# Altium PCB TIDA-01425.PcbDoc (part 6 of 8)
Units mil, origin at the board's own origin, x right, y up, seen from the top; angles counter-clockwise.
Board outline 7000 x 3600 mil, 6 copper layers (Layer 1 - Top Layer, Layer 2 - GND, Layer 3 - Signal / PWR, Layer 4 - Signal / PWR, Layer 5 - PWR, Layer 6 - Bottom Layer), stack 60.4 mil thick; 495 components, 307 nets, 2058 pads, 1870 vias.
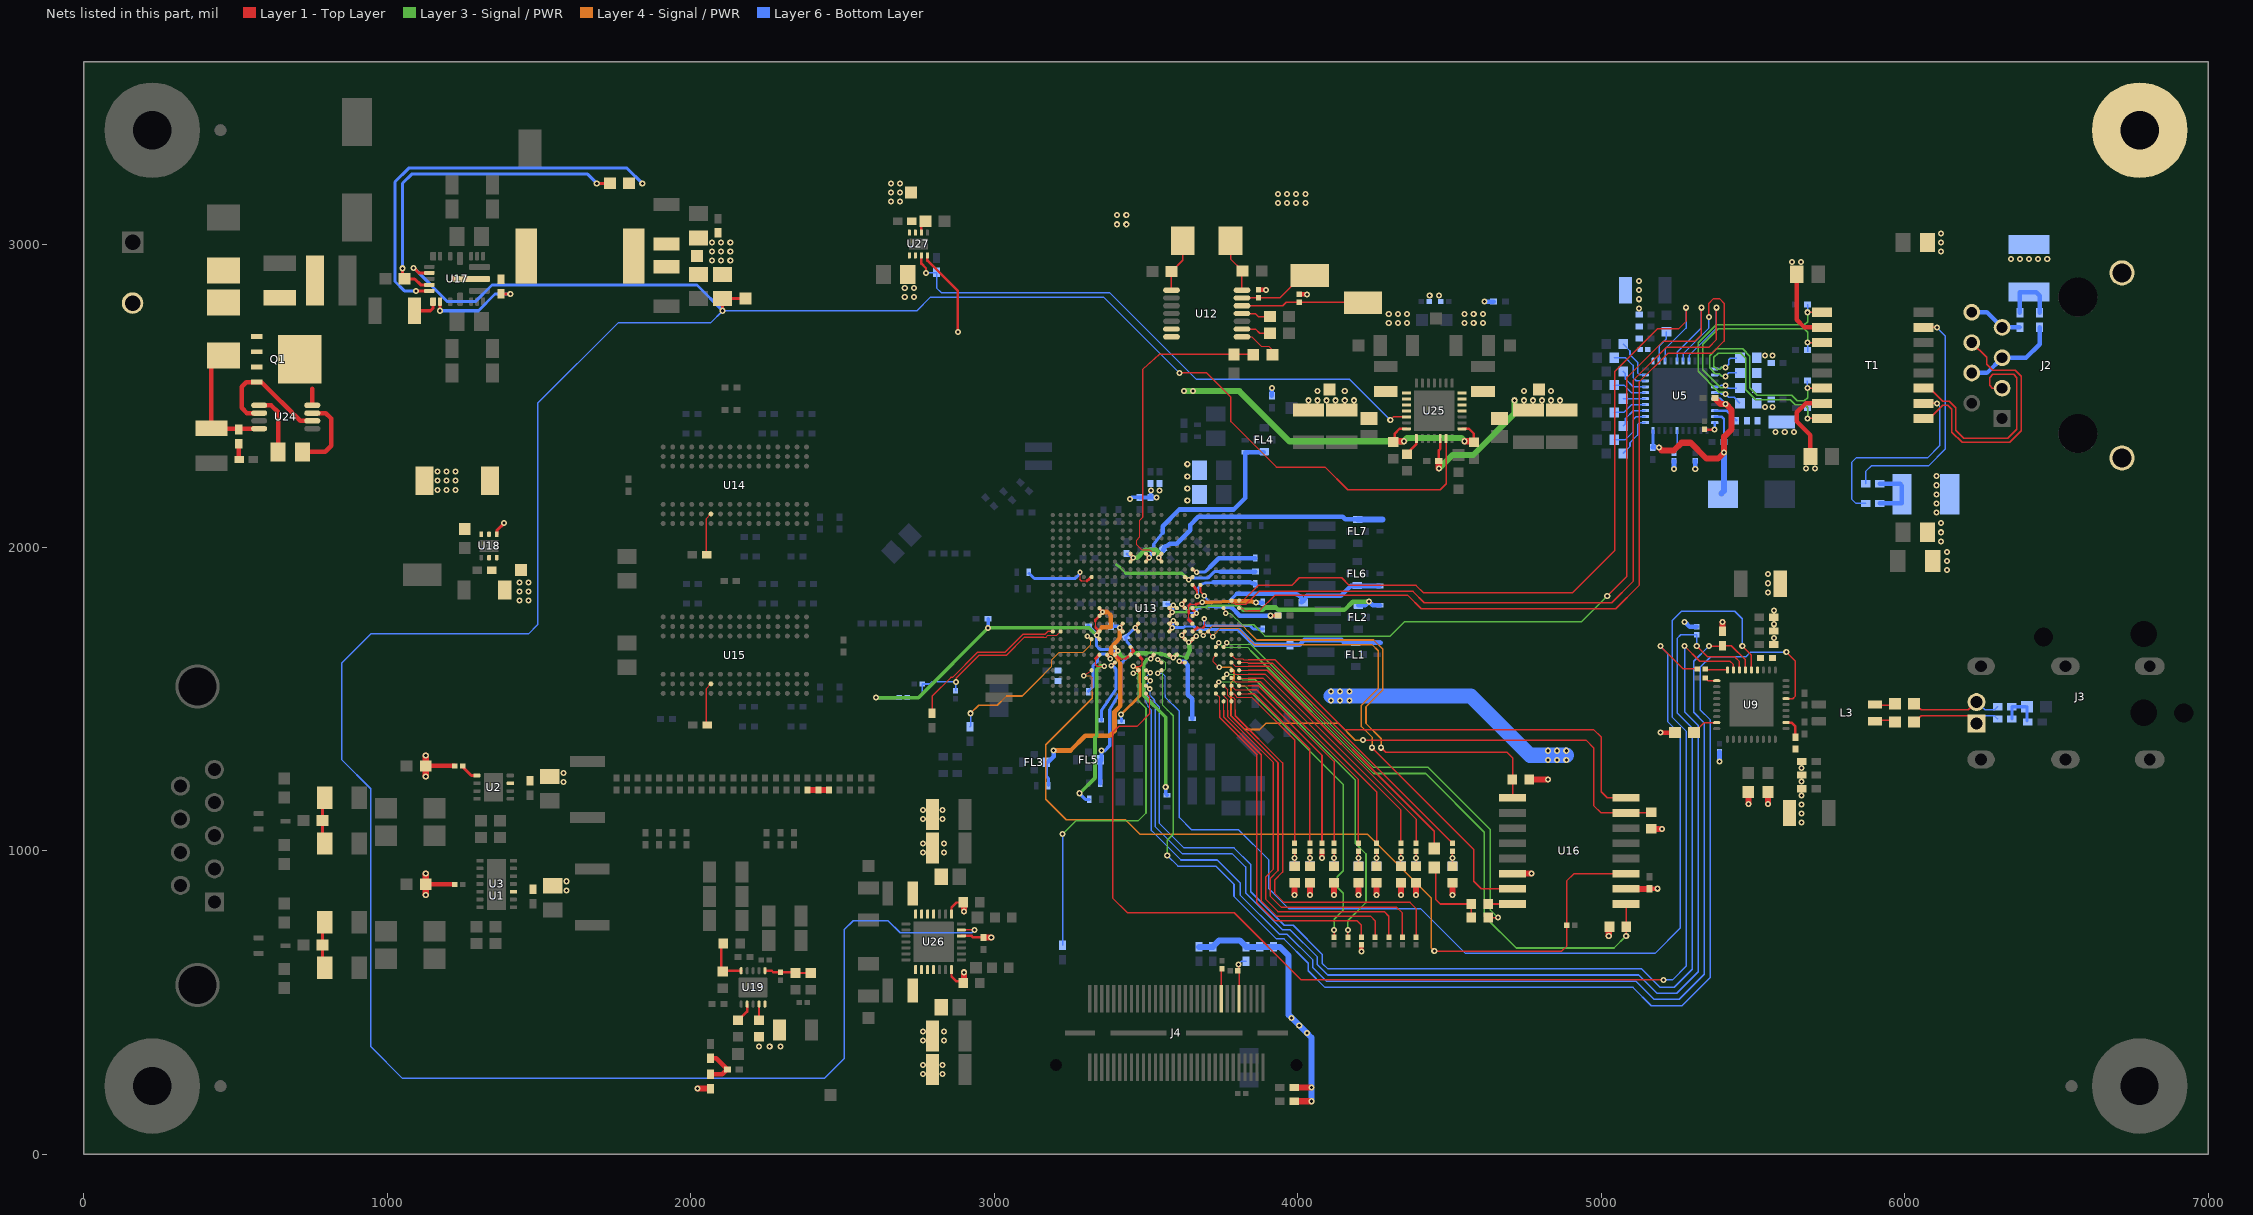
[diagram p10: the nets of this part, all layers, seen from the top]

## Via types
v1: diameter 20, hole 10, Layer 1 - Top Layer to Layer 6 - Bottom Layer, tented both sides, 1119 vias
v2: diameter 20, hole 9.99, Layer 1 - Top Layer to Layer 6 - Bottom Layer, tented both sides, 298 vias
v3: diameter 18, hole 7.99, Layer 1 - Top Layer to Layer 6 - Bottom Layer, tented both sides, 203 vias
v4: diameter 18, hole 8, Layer 1 - Top Layer to Layer 6 - Bottom Layer, tented both sides, 177 vias
v5: diameter 19.68, hole 7.87, Layer 1 - Top Layer to Layer 6 - Bottom Layer, tented both sides, 41 vias
v6: diameter 20, hole 10, Layer 1 - Top Layer to Layer 6 - Bottom Layer, 27 vias
v7: diameter 19.68, hole 7.87, Layer 1 - Top Layer to Layer 6 - Bottom Layer, 5 vias

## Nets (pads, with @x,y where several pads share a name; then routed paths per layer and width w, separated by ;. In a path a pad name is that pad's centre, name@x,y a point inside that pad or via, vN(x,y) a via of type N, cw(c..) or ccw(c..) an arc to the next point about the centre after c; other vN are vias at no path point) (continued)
MII0_TX_D1: U5.5 U13.N3 | length 2709.4
  Layer 1 - Top Layer w4: U13.N3@3755.91,1800 v3(3763.5,1783.6)
  Layer 1 - Top Layer w5: v2(5020,1840) 5085,1905 5085,2560 5205,2680 5310,2680 5330,2700 v6(5330,2790)
  Layer 3 - Signal / PWR w4: v3(3763.5,1783.6) 3778,1783.6 3816.47,1745.13 3837,1745.13
  Layer 3 - Signal / PWR w5.25: 3837,1745.13 3854.87,1745.13 3892,1708 4305,1708 4352,1755 4935,1755 v2(5020,1840)
  Layer 6 - Bottom Layer w5: U5.5@5250.16,2614.17 5250.16,2643.16 5330,2723 v6(5330,2790)
MII0_TX_D2: U5.6 U13.N1 | length 2811.6
  Layer 1 - Top Layer w4: U13.N1@3807.09,1800 3817.02,1800 3825.12,1791.9 3837,1791.9
  Layer 1 - Top Layer w5: 3837,1791.9 3874.09,1791.9 3924.2,1842 4363,1842 4407,1798 5048,1798 5125,1875 5125,2545 5220,2640 5365,2640 5405,2680 5405,2805 5390,2820 5370,2820 5355,2805 v6(5355,2760)
  Layer 6 - Bottom Layer w5: U5.6@5269.84,2614.17 5269.84,2637.84 5355,2723 v6(5355,2760)
MII0_TX_D3: U5.7 U13.P2 | length 2701.7
  Layer 1 - Top Layer w4: U13.P2@3781.5,1825.59 3794.19,1812.9 3829.15,1812.9
  Layer 1 - Top Layer w5: 3829.15,1812.9 3871.26,1855 4380,1855 4417,1818 5035,1818 5105,1888 5105,2550 5215,2660 5355,2660 5380,2685 v6(5380,2790)
  Layer 6 - Bottom Layer w5: U5.7@5289.53,2614.17 5289.53,2632.53 5380,2723 v6(5380,2790)
MII0_TX_EN: U5.3 U13.P1 | length 2490.3
  Layer 1 - Top Layer w4: U13.P1@3807.09,1825.59 3820.59,1825.59 3837,1842
  Layer 1 - Top Layer w5: 3837,1842 3840.99,1845.99 3841.14,1845.99 3870.16,1875 3980,1875 4005,1900 4145,1900 4170,1875 4390,1875 4415,1850 4905,1850 5045,1990 5045,2580 5185,2720 5255,2720 5280,2745 v6(5280,2790)
  Layer 6 - Bottom Layer w5: U5.3@5210.79,2614.17 5210.79,2653.79 5280,2723 v6(5280,2790)
NetC2_1: C2.1 R5.1 R7.2 | length 155.3
  Layer 1 - Top Layer w10: R7.2@792.91,615 786.5,621.42 C2.1@786.5,690 786.5,758.58 R5.1@792.91,765
NetC8_2: C8.2 C11.2 C12.2 C13.1 U5.16 U5.19 U5.30 | length 882.3
  Layer 1 - Top Layer w20: v1(5190,2329.69) 5199.69,2320 5240,2320 5265,2345 5295,2345 5347,2293 5385,2293 v1(5405,2313) 5405,2365 5430,2390 5430,2453 v1(5410,2473) 5393,2473 C8.2@5374.69,2491.31
  Layer 6 - Bottom Layer w8: U5.19@5374.17,2431.1 5396.9,2431.1 5404.69,2423.31 C12.2@5404.69,2348 ; U5.16@5374.17,2490.16 5392.84,2490.16 v1(5410,2473)
  Layer 6 - Bottom Layer w10: C11.2@5171.42,2329.69 U5.30@5171.42,2385.83
  Layer 6 - Bottom Layer w15: C11.2@5170,2329.69 5171.42,2329.69 v1(5190,2329.69)
  Layer 6 - Bottom Layer w20: C13.1@5396.5,2178 5404.69,2186.19 C12.2@5404.69,2348
NetC15_1: C15.1 C31.1 FL1.3 U13.K10 U13.L9 U13.L10 | length 810.9
  Layer 1 - Top Layer w10: U13.K10@3576.77,1723.23 v3(3586.5,1736) U13.L10@3576.77,1748.82 v3(3589.8,1758.7) U13.L9@3602.36,1748.82
  Layer 6 - Bottom Layer w6: 3627.2,1739 3659.2,1739
  Layer 6 - Bottom Layer w10: v3(3586.5,1736) 3624.2,1736 3627.2,1739 ; 3659.2,1739 3669.19,1729.01 3806.2,1729.01 3808.71,1726.5
  Layer 6 - Bottom Layer w12: v3(3586.5,1736) v3(3589.8,1758.7)
  Layer 6 - Bottom Layer w15: 3808.71,1726.5 3855.83,1679.38 C15.1@3975,1679.38 4006.38,1679.38 4022,1695 4144.3,1695 4152.93,1686.37 FL1.3@4191,1686.37 4274,1686.37
NetC20_1: C20.1 J3.2 R27.2 | length 306.3
  Layer 1 - Top Layer w5: C20.1@6031.5,1485 6055,1465 6210,1465 J3.2@6236.93,1490.43
  Layer 6 - Bottom Layer w5: J3.2@6236.93,1490.43 6265,1465 6296.38,1465 R27.2@6306.38,1475
NetC20_2: C20.2 L3.1 | length 70
  Layer 1 - Top Layer w5: L3.1@5900,1480 C20.2@5970,1480
NetC26_1: C26.1 J3.1 R26.2 | length 306.3
  Layer 1 - Top Layer w5: C26.1@6031.5,1425 6055,1445 6210,1445 J3.1@6236.93,1419.57
  Layer 6 - Bottom Layer w5: J3.1@6236.93,1419.57 6265,1445 6296.38,1445 R26.2@6306.38,1435
NetC26_2: C26.2 L3.4 | length 70
  Layer 1 - Top Layer w5: L3.4@5900,1430 C26.2@5970,1430
NetC28_1: C28.1 R26.1 R27.1 R28.2 | length 132
  Layer 6 - Bottom Layer w10: R26.1@6353.62,1435 R27.1@6353.62,1475 C28.1@6398.5,1475 ; R28.2@6403.5,1427.87 C28.1@6403.5,1475
NetC34_1: C34.1 C35.1 FL2.3 U13.M10 U13.N9 U13.N10 | length 871.1
  Layer 1 - Top Layer w10: U13.M10@3576.77,1774.41 v3(3586.7,1787.1) U13.N10@3576.77,1800 v3(3589.6,1809.6) U13.N9@3602.36,1800
  Layer 3 - Signal / PWR w6: 3666.99,1803.01 3699.01,1803.01
  Layer 3 - Signal / PWR w8: v3(3586.7,1787.1) 3632.1,1787.1 3648.01,1803.01 3666.99,1803.01 ; 3699.01,1803.01 3703.58,1807.58 3749.45,1807.58 3750.5,1808.63 3806.37,1808.63 3820,1795
  Layer 3 - Signal / PWR w15: 3820,1795 3884.99,1795 3892.09,1802.1 3927.91,1802.1 3936.01,1794 4154,1794 4181.2,1821.2 v1(4234.9,1821.2)
  Layer 6 - Bottom Layer w10: C34.1@3567.5,1813 v3(3589.6,1809.6)
  Layer 6 - Bottom Layer w12: v3(3586.7,1787.1) v3(3589.6,1809.6)
  Layer 6 - Bottom Layer w15: FL2.3@4200,1809 4222.7,1809 v1(4234.9,1821.2) 4247.1,1809 C35.1@4271.2,1809
NetC36_1: C36.1 C41.1 FL3.3 U13.K16 U13.L16 | length 784.7
  Layer 1 - Top Layer w10: U13.K16@3423.23,1723.23 v3(3413.4,1736) U13.L16@3423.23,1748.82
  Layer 4 - Signal / PWR w10: 3384.7,1653.6 3392.5,1648.1 3401.21,1639.39 3415,1616.64
  Layer 4 - Signal / PWR w15: v1(3195.8,1330.81) 3251.33,1330.81 3299.34,1379.87 3381.07,1379.87 3396.2,1395 3396.2,1458.71 3401.46,1464 3415,1477.62 3415,1616.64 ; 3384.7,1653.6 3385.9,1669.9 3413.1,1702.2 v3(3413.4,1736)
  Layer 6 - Bottom Layer w10: FL3.3@3171.37,1292 3171.37,1245.63 3178,1239 C41.1@3178,1215 ; FL3.3@3176.4,1291.7 FL3.3@3179.7,1295 ; C36.1@3387.1,1740.3 3409.1,1740.3 v3(3413.4,1736)
  Layer 6 - Bottom Layer w15: FL3.3@3179.7,1295 3195.8,1311.1 v1(3195.8,1330.81)
NetC37_1: C37.1 U13.F17 | length 222.3
  Layer 1 - Top Layer w10: v3(3385,1610.9) U13.F17@3397.64,1620.87
  Layer 6 - Bottom Layer w10: C37.1@3353,1429 3353,1462.95 3354.05,1464 3400.79,1532.31 3400.79,1600 3390.79,1610 3385.9,1610 v3(3385,1610.9)
NetC38_1: C38.1 U13.G14 | length 289.5
  Layer 1 - Top Layer w4: v3(3458.6,1608.8) 3461.8,1608.8 3462.6,1608 3481.5,1608 ; 3487.1,1613.6 3487.1,1630.94
  Layer 1 - Top Layer w6: 3481.5,1608 3487.1,1613.6
  Layer 1 - Top Layer w10: U13.G14@3474.41,1646.46 3487.1,1630.94
  Layer 4 - Signal / PWR w10: v2(3417.7,1449.8) 3479.6,1510.3 3479,1598.1 v3(3458.6,1608.8)
  Layer 6 - Bottom Layer w10: v2(3417.7,1449.8) C38.1@3418.6,1426.2
NetC39_1: C39.1 U13.T7 | length 265.3
  Layer 1 - Top Layer w6: 3666.3,1861.5 v3(3669.5,1839.3)
  Layer 1 - Top Layer w10: U13.T7@3653.54,1876.77 3666.3,1861.5
  Layer 6 - Bottom Layer w10: v3(3669.5,1839.3) 3669.5,1862.13 3684.2,1880.2 3695.3,1882.27 3721.17,1884.9
  Layer 6 - Bottom Layer w15: 3721.17,1884.9 3842.8,1884.9 3859.62,1878.93 C39.1@3859.7,1878.9
NetC40_1: C40.1 U13.F8 | length 236.5
  Layer 1 - Top Layer w8: v3(3609.3,1625.1) 3613.53,1620.87 U13.F8@3627.95,1620.87
  Layer 6 - Bottom Layer w15: v3(3609.3,1625.1) 3627.03,1622.77 3627.23,1622.77 3637.85,1612.15 3637.85,1515.15 3652,1501 C40.1@3652,1435
NetC42_1: C42.1 C46.1 FL4.3 U13.W13 U13.Y13 | length 673.9
  Layer 1 - Top Layer w10: U13.W13@3500,1953.54 v3(3510.05,1966.35) U13.Y13@3500,1979.13
  Layer 6 - Bottom Layer w10: v3(3510.05,1966.35) 3525.5,1989 3525.5,2010.5 3555,2048.81
  Layer 6 - Bottom Layer w15: 3555,2048.81 3555,2070 3610,2125 3789,2125 3827,2163 C46.1@3827,2314 FL4.3@3888.37,2314
NetC43_1: C43.1 U13.G19 | length 572.7
  Layer 1 - Top Layer w4: 3333.6,1614 3333.6,1633.6 ; 3339.6,1608 3362,1608 v3(3362.9,1608.9)
  Layer 1 - Top Layer w6: 3333.6,1614 3339.6,1608
  Layer 1 - Top Layer w10: 3333.6,1633.6 U13.G19@3346.4,1646.4
  Layer 3 - Signal / PWR w12: v1(3281.5,1190) 3332,1240.5 3332,1372 3338,1378 3338,1598.4 3349.1,1609.5 3362.3,1609.5 v3(3362.9,1608.9)
  Layer 6 - Bottom Layer w10: v1@3280,1190 3300,1170 C43.1@3313,1170
NetC44_1: C44.1 U13.K7 | length 286.6
  Layer 1 - Top Layer w4: 3669.79,1736 3688,1736 ; v3(3691.8,1764.3) 3692.1,1740.1
  Layer 1 - Top Layer w8: 3688,1736 3692.1,1740.1
  Layer 1 - Top Layer w10: U13.K7@3653.54,1723.23 3669.79,1736
  Layer 6 - Bottom Layer w8: v3(3691.8,1764.3) 3691.8,1748.2 3698,1742 3843,1742
  Layer 6 - Bottom Layer w10: 3843,1742 3853.5,1731.5 C44.1@3886.5,1731.5
NetC45_1: C45.1 U13.U20 | length 255.7
  Layer 1 - Top Layer w4: 3282.5,1894 v3(3282.5,1918.7) ; 3286.9,1889.6 3305.02,1889.6
  Layer 1 - Top Layer w6: 3282.5,1894 3286.9,1889.6
  Layer 1 - Top Layer w10: 3305.02,1889.6 U13.U20@3320.87,1902.36
  Layer 6 - Bottom Layer w10: C45.1@3114.8,1914 3115.6,1914 3131.79,1897.81 3267.16,1897.81 3282.5,1913.15 v3(3282.5,1918.7)
NetC47_1: C47.1 C50.1 FL5.3 U13.K14 U13.L14 | length 617.2
  Layer 1 - Top Layer w10: U13.K14@3474.41,1723.23 v3(3464.6,1736) U13.L14@3474.41,1748.82
  Layer 6 - Bottom Layer w10: 3380.5,1465.59 3417,1527.02 3417,1617.01 3427.76,1627.77 3453,1648.43 3453,1670.56 3439.37,1686.25 3438.46,1687.29 3438.17,1688.16 3432.9,1703.92 3434.14,1705.17 3446.82,1718.01 3446.96,1718.01 3457.49,1728.54 3457.49,1728.8 v3(3464.6,1736)
  Layer 6 - Bottom Layer w12: FL5.3@3349.94,1293.33 3353.2,1296.6 v1(3353.2,1330.4) 3363.63,1330.4 3380.5,1347.27 3380.5,1465.59
  Layer 6 - Bottom Layer w15: C50.1@3349,1223 3349,1298.63 FL5.3@3350.37,1300
NetC48_1: C48.1 C56.1 FL6.3 U13.T6 | length 687.3
  Layer 1 - Top Layer w6: U13.T6@3679.13,1876.77 3679.13,1854.77 v3(3692.6,1841.3)
  Layer 6 - Bottom Layer w8: v3(3692.6,1841.3) 3705.74,1821.45 3714.25,1820.79 3773.04,1821.2
  Layer 6 - Bottom Layer w12: 3773.04,1821.2 3799.2,1847.5
  Layer 6 - Bottom Layer w15: 3799.2,1847.5 3992.27,1847.5 4009.14,1837.68 4014.71,1826.61 C48.1@4012.72,1820.59 ; C56.1@4271,1873 4174.51,1873 4142.4,1840.9 4030.31,1840.9 4018.21,1822.12 4016.8,1821.82 4012.98,1820.99 C48.1@4012.72,1820.59 ; C48.1@4012.72,1820.59 4011.91,1819.32 4013.41,1819.22 C48.1@4012.72,1820.59
NetC51_1: C51.1 C57.1 C239.1 FL7.3 U13.W11 U13.W15 U13.Y11 U13.Y15 | length 1014.7
  Layer 1 - Top Layer w10: U13.W15@3448.82,1953.54 v3(3458.3,1966.4) U13.Y15@3448.82,1979.13 ; U13.W11@3551.2,1953.6 v3(3541.4,1966.5) U13.Y11@3551.18,1979.13 U13.Y11@3551.2,1979.2
  Layer 3 - Signal / PWR w15: v3(3458.3,1966.4) 3471.4,1966.4 3496.93,1991.93 3533.07,1991.93 3541.4,1983.6 v3(3541.4,1966.5)
  Layer 6 - Bottom Layer w10: C51.1@3438,1978 v3(3458.3,1966.4)
  Layer 6 - Bottom Layer w15: v3(3541.4,1966.5) 3550.77,1982.63 3556.9,1993.18 3559.43,1997.55 3560.99,2000.24 3562.41,2002.68 3563.02,2003.74 3572.25,2006.63 3578.31,2012.69 3600.99,2012.69 3645.51,2057.21 3645.51,2074.19 3672.22,2100.9 4148,2100.9 4156.53,2092.37 FL7.3@4198,2092.37
  Layer 6 - Bottom Layer w20: FL7.3@4198,2092.37 C57.1@4280,2092.37
NetC52_1: C52.1 U13.G18 | length 194.3
  Layer 1 - Top Layer w10: U13.G18@3372,1646.4 v3(3381.8,1633.1)
  Layer 6 - Bottom Layer w10: C52.1@3310,1525 3324.83,1539.83 3324.83,1550.38 3325.69,1551.24 3325.69,1610.69 3340,1625 3340,1636.85 3351.84,1648.69 3366.76,1648.69 3381.8,1633.65 v3(3381.8,1633.1)
NetC53_1: C53.1 U13.G12 | length 510.4
  Layer 1 - Top Layer w10: v3(3515.9,1633.8) U13.G12@3525.6,1646.4
  Layer 3 - Signal / PWR w12: v3(3515.9,1633.8) 3504,1631 3493,1617 3493,1512 3565,1440 v1(3565,1210)
  Layer 6 - Bottom Layer w12: v1(3565,1210) 3565,1188 C53.1@3569,1184
NetC54_1: C54.1 U13.V7 | length 228.9
  Layer 1 - Top Layer w10: U13.V7@3653.54,1927.95 v3(3666.5,1918.4)
  Layer 6 - Bottom Layer w10: v3(3666.5,1918.4) 3693.4,1918.4 3710,1935
  Layer 6 - Bottom Layer w15: 3710,1935 3740,1965 C54.1@3860,1965
NetC55_1: C55.1 U13.L7 | length 311.5
  Layer 1 - Top Layer w4: 3640.7,1761.7 3640.7,1782.5 ; 3640.7,1792.16 3640.7,1808.02 ; 3645.48,1812.8 3665.16,1812.8
  Layer 1 - Top Layer w8: 3640.7,1782.5 3640.7,1792.16 ; 3640.7,1808.02 3645.48,1812.8
  Layer 1 - Top Layer w10: 3640.7,1761.7 U13.L7@3653.6,1748.8 ; 3665.16,1812.8 v3(3685.3,1819)
  Layer 4 - Signal / PWR w12: v3(3685.3,1819) 3717.45,1819 3782.6,1823.1
  Layer 4 - Signal / PWR w15: 3782.6,1823.1 3846.27,1823.1 v2(3863.1,1818.4)
  Layer 6 - Bottom Layer w15: v2(3863.1,1818.4) C55.1@3884,1818.4
NetC121_1: C121.1 L5.1 U17.9
NetC121_2: C121.2 U17.2 | length 315.2
  Layer 1 - Top Layer w10: v1(1173.62,2780) U17.2@1173.62,2810.2 ; C121.2@1374.72,2836.38 1376.1,2835 v1(1405,2835)
  Layer 6 - Bottom Layer w10: v1(1173.62,2780) 1300,2780 1355,2835 v1(1405,2835)
NetC145_1: C145.1 R22.1 R42.1 | length 206.6
  Layer 6 - Bottom Layer w15: R42.1@5918.62,2145 5991.26,2145 C145.1@5991.26,2175 5991.26,2203.74 5985,2210 R22.1@5918.62,2210
NetC161_1: C161.1 R150.1 R151.2 | length 155.3
  Layer 1 - Top Layer w10: R151.2@792.91,1025 786.5,1031.42 C161.1@786.5,1100 786.5,1168.58 R150.1@792.91,1175
NetC165_1: C165.1 C166.1 D2.1 J5.2 Q1.1 Q1.2 Q1.3 U24.4 | length 358.5
  Layer 1 - Top Layer w15: D2.1@420,2592.99 C166.1@420,2392.09 420.47,2391.61 U24.4@577.4,2391.61
NetC165_2: C165.2 C167.2 | length 52.8
  Layer 1 - Top Layer w15: C167.2@510,2288.62 C165.2@510,2341.38
NetC168_1: C168.1 L4.1 Q1.5 U24.8 | length 54.2
  Layer 1 - Top Layer w15: U24.8@752.6,2468.39 752.6,2522.6
NetC178_1: C178.1 R61.1 U17.21 | length 1115.6
  Layer 1 - Top Layer w10: v1(1050,2920) 1050,2891.5 C178.1@1056.5,2885 1090,2885 1109.68,2865.31 U17.21@1138.19,2865.31 ; v1(1690,3200) R61.1@1733.23,3200
  Layer 6 - Bottom Layer w10: v1(1050,2920) 1050,3200 1080,3230 1660,3230 v1(1690,3200)
NetC183_1: C183.1 U17.1 | length 86.2
  Layer 1 - Top Layer w10: C183.1@1089.68,2780 1142,2780 1150.98,2788.98 U17.1@1150.98,2810.2
NetC191_1: C191.1 R73.1 U19.5 | length 145.1
  Layer 1 - Top Layer w8: R73.1@2100,687.56 2100,607.56 C191.1@2105,602.56 ; C191.1@2107.57,605.12 U19.5@2165.63,605.12
NetC193_1: C193.1 R75.2 R79.1 U19.1 | length 153.8
  Layer 1 - Top Layer w8: U19.1@2244.37,605.12 2266.81,605.12 2271.94,599.99 C193.1@2295,599.99 2342.57,599.99 R79.1@2345,597.56 R75.2@2395,597.56
NetC194_1: C194.1 U12.14 Y1.1 | length 182.1
  Layer 1 - Top Layer w5: Y1.1@3778.74,3010.92 3778.74,2950.68 3816.14,2913.28 U12.14@3816.14,2847.69
  Layer 1 - Top Layer w10: C194.1@3816.14,2913.28 C194.1@3818.5,2910.92
NetC200_2: C200.2 R89.2 R90.2 | length 60
  Layer 1 - Top Layer w20: R90.2@2390,1200.31 R89.2@2420,1200.31 C200.2@2450,1200.31
NetC201_1: C201.1 R92.1 R94.1 | length 193.7
  Layer 6 - Bottom Layer w15: R94.1@6380,2773.62 6380,2841.26 C201.1@6410,2841.26 6433.74,2841.26 6445,2830 R92.1@6445,2773.62
NetC222_1: C222.1 U12.1 Y1.2 | length 178.7
  Layer 1 - Top Layer w5: U12.1@3583.86,2847.69 C222.1@3583.86,2909.42 ; C222.1@3584,2909.42 3621.26,2946.68 Y1.2@3621.26,3010.92
NetC224_1: C224.1 U24.7 | length 263.1
  Layer 1 - Top Layer w15: C224.1@720,2315 795,2315 815,2335 815,2425 797.2,2442.8 U24.7@752.6,2442.8
NetC224_2: C224.2 U24.1 | length 202.3
  Layer 1 - Top Layer w15: U24.1@577.4,2468.39 616.61,2468.39 640,2445 C224.2@640,2315
NetC231_1: C231.1 R114.2 R116.1 U13.K24 | length 648.3
  Layer 1 - Top Layer w4: 3163,1704.74 3170.72,1704.74 3176.31,1710.33 3205.67,1710.33 3205.74,1710.4 3205.74,1710.47 U13.K24@3218.5,1723.23
  Layer 1 - Top Layer w5: v1(2873.24,1556.76) 2875,1558.52 2875,1570 2950,1645 3040,1645 3099.74,1704.74 3163,1704.74
  Layer 6 - Bottom Layer w5: R116.1@2715,1505 2750.01,1505 2762.99,1517.98 C231.1@2762.99,1550 2787.24,1550 2794,1556.76 v1(2873.24,1556.76) 2873.24,1528.24 R114.2@2873,1527.99
NetC249_1: C249.1 U25.1 | length 63.7
  Layer 1 - Top Layer w8: C249.1@4360,2307.56 4360,2310 4390.94,2340.94 U25.1@4390.94,2358.46
NetC271_1: C271.1 U27.6 | length 49.1
  Layer 1 - Top Layer w8: U27.6@2759.84,3037.4 2759.84,3057.84 2777,3075 C271.1@2781.38,3075
NetD2_2: D2.2 D3.2
NetJ2_4: J2.4 J2.5 R92.2 | length 319.5
  Layer 6 - Bottom Layer w15: J2.4@6221.26,2575 6271.26,2575 J2.5@6321.26,2625 6400,2625 6445,2670 R92.2@6445,2726.38
NetJ2_7: J2.7 J2.8 R94.2 | length 178.1
  Layer 6 - Bottom Layer w15: J2.8@6221.26,2775 6271.26,2775 J2.7@6321.26,2725 R94.2@6378.62,2725
NetJ4_15: J4.15 R59.2 | length 100.2
  Layer 1 - Top Layer w5.25: J4.15@3747.64,512.8 3747.64,609.65 R59.2@3750,612.01
NetL2_1: L2.1 U25.22 U25.23
NetL6_2: L6.2 U18.5
NetL12_1: L12.1 U25.13 U25.14
NetL13_1: L13.1 U26.22 U26.23
NetL14_1: L14.1 U26.13 U26.14
NetQ1_4: Q1.4 U24.2 U24.6 | length 426.3
  Layer 1 - Top Layer w15: U24.2@577.4,2442.8 537.2,2442.8 520,2460 520,2530 535,2545 Q1.4@569.57,2545 585,2545 712.8,2417.2 U24.6@752.6,2417.2
NetR1_1: R1.1 U12.11 | length 96.5
  Layer 1 - Top Layer w5: U12.11@3816.14,2770.92 3860,2770.92 3870,2760.92 R1.1@3908.5,2760.92
NetR15_2: R15.2 U5.1
NetR16_2: R16.2 U5.26 | length 80
  Layer 6 - Bottom Layer w5: R16.2@5240,2312 R16.2@5240,2310.99 5250.16,2321.15 U5.26@5250.16,2385.83
NetR17_2: R17.2 U5.2 | length 106.2
  Layer 6 - Bottom Layer w5: U5.2@5191.1,2614.17 5191.1,2664.1 5215,2688 R17.2@5215,2710.44
NetR19_1: R19.1 U12.9 | length 98.1
  Layer 1 - Top Layer w5: U12.9@3816.14,2719.74 3861.18,2719.74 3875,2705.92 R19.1@3908.5,2705.92
NetR20_2: R20.2 U5.35 | length 73.1
  Layer 6 - Bottom Layer w5: R20.2@5072.72,2490.16 U5.35@5145.83,2490.16
NetR21_1: R21.1 U5.20 | length 58.4
  Layer 1 - Top Layer w8: R21.1@5340,2389.85 5341.85,2388 v1(5374.17,2388)
  Layer 6 - Bottom Layer w8: v1(5374.17,2388) U5.20@5374.17,2411.42
NetR22_2: R22.2 T1.15 | length 793.3
  Layer 1 - Top Layer w5: T1.15@6058.58,2725 v1(6106.1,2725)
  Layer 6 - Bottom Layer w5: R22.2@5871.38,2210 5871.38,2250 5891.38,2270 6080,2270 6134,2324 6134,2697.1 v1(6106.1,2725)
NetR23_2: R23.2 U9.22
NetR24_2: R24.2 U9.11 | length 78.2
  Layer 1 - Top Layer w8: U9.11@5609.17,1422.94 5627.06,1422.94 5640,1410 R24.2@5640,1374.69 R24.2@5640,1367.99
NetR25_2: R25.2 U9.28 | length 43.8
  Layer 1 - Top Layer w5: R25.2@5342.99,1570 5352.25,1560.74 U9.28@5380.83,1560.74 ; R25.2@5345,1575 R25.2@5346.5,1573.5
NetR29_2: R29.2 U9.27 | length 73.8
  Layer 1 - Top Layer w5: R29.2@5342.99,1595 5344.17,1596.17 U9.27@5416.26,1596.17
NetR30_1: R30.1 U12.8 | length 134.8
  Layer 1 - Top Layer w4: U12.8@3816.14,2694.15 3848.94,2694.15 3879.55,2663.54 3905,2663.54 3916.5,2652.05 R30.1@3916.5,2635
NetR31_1: R31.1 SDA_CLK.1 U12.13 | length 254.4
  Layer 1 - Top Layer w5: U12.13@3816.14,2822.1 R31.1@3869.17,2822.1 ; R31.1@3870,2822.93 3942.01,2822.93 SDA_CLK.1@4015,2895.92
  Layer 1 - Top Layer w10: R31.1@3869.17,2822.1 R31.1@3870,2822.93 ; SDA_CLK.1@4015,2895.92 SDA_CLK.1@4040,2895.92
NetR36_2: R36.2 U14.L8 | length 147.2
  Layer 1 - Top Layer w4: 2050.52,2094.77 U14.L8@2066.26,2110.51
  Layer 1 - Top Layer w5: R36.2@2050,1970 2050.52,1970.52 2050.52,2094.77
NetR37_2: R37.2 U15.L8 | length 147.2
  Layer 1 - Top Layer w4: 2050.52,1534.77 U15.L8@2066.26,1550.51
  Layer 1 - Top Layer w5: R37.2@2050,1410 2050.52,1410.52 2050.52,1534.77
NetR38_1: R38.1 U16.16 | length 80.4
  Layer 1 - Top Layer w8: R38.1@4627.56,825 U16.16@4707.99,825
NetR40_2: R40.2 U13.F2 | length 955.2
  Layer 1 - Top Layer w4: U13.F2@3781.5,1620.87 3794.27,1608.1 3837,1608.1
  Layer 1 - Top Layer w5: 3837,1608.1 3906.9,1608.1 4450,1065 R40.2@4450,1008.5
NetR42_2: R42.2 T1.10 | length 676.6
  Layer 1 - Top Layer w5: T1.10@6058.58,2475 v1(6106.1,2475)
  Layer 6 - Bottom Layer w5: R42.2@5871.38,2145 5840,2145 5825,2160 5825,2280 5840,2295 6075,2295 6115,2335 6115,2466.1 v1(6106.1,2475)
NetR43_1: R43.1 R44.1 R100.1 | length 76.9
  Layer 1 - Top Layer w5: R44.1@4510,949.57 v1(4510,977.01) R100.1@4510,999.02
  Layer 6 - Bottom Layer w5: R43.1@4510,949.57 v1(4510,977.01)
NetR45_1: R45.1 R46.1 R104.1 | length 76.9
  Layer 1 - Top Layer w5: R46.1@4340,949.57 v1(4340,977.01) R104.1@4340,999.02
  Layer 6 - Bottom Layer w5: R45.1@4340,949.57 v1(4340,977.01)
NetR47_1: R47.1 R101.1 R108.1 | length 76.9
  Layer 1 - Top Layer w5: R101.1@4390,949.57 v1(4390,977.01) R108.1@4390,999.02
  Layer 6 - Bottom Layer w5: R47.1@4390,949.57 v1(4390,977.01)
NetR48_1: R48.1 SCL_CLK.1 U12.12 | length 401.6
  Layer 1 - Top Layer w5: U12.12@3816.14,2796.51 3950.59,2796.51 3962.01,2807.93 R48.1@4005,2807.93 SCL_CLK.1@4212.99,2807.93
NetR69_1: R69.1 U19.7 | length 66.4
  Layer 1 - Top Layer w8: R69.1@2155,442.56 2157.56,442.56 2185.32,470.31 U19.7@2185.32,494.88
NetR70_1: R70.1 U19.9 | length 52.5
  Layer 1 - Top Layer w8: U19.9@2224.69,494.88 2224.69,442.87 R70.1@2225,442.56
NetR96_2: R96.2 R97.1 R145.2 | length 132.5
  Layer 1 - Top Layer w15: R96.2@2065,263.62 2103.94,263.62 R145.2@2120.31,280 2083.94,316.38 R97.1@2065,316.38
NetR102_1: R102.1 R105.1 R112.1 | length 76.9
  Layer 1 - Top Layer w5: R102.1@4120,949.57 v1(4120,977.01) R112.1@4120,999.02
  Layer 6 - Bottom Layer w5: R105.1@4120,949.57 v1(4120,977.01)
NetR106_1: R106.1 R109.1 R118.1 | length 76.9
  Layer 1 - Top Layer w5: R109.1@4260,949.57 v1(4260,977.01) R118.1@4260,999.02
  Layer 6 - Bottom Layer w5: R106.1@4260,949.57 v1(4260,977.01)
NetR110_1: R110.1 R113.1 R122.1 | length 76.9
  Layer 1 - Top Layer w5: R113.1@4200,949.57 v1(4200,977.01) R122.1@4200,999.02
  Layer 6 - Bottom Layer w5: R110.1@4200,949.57 v1(4200,977.01)
NetR115_1: R115.1 R119.1 R126.1 | length 76.9
  Layer 1 - Top Layer w5: R115.1@4040,949.57 v1(4040,977.01) R126.1@4040,999.02
  Layer 6 - Bottom Layer w5: R119.1@4040,949.57 v1(4040,977.01)
NetR120_1: R120.1 R123.1 R129.1 | length 76.9
  Layer 1 - Top Layer w5: R120.1@3990,949.57 v1(3990,977.01) R129.1@3990,999.02
  Layer 6 - Bottom Layer w5: R123.1@3990,949.57 v1(3990,977.01)
NetR133_1: R133.1 U13.E14 | length 1175.1
  Layer 1 - Top Layer w4: v3(3458.03,1586) 3462.29,1585.48 U13.E14@3474.41,1595.28
  Layer 3 - Signal / PWR w4: v3(3458.03,1586) 3469,1586 3475,1580 3475,1494.99
  Layer 3 - Signal / PWR w5.25: v1(3225,1055) 3270,1100 3475,1100 3500,1125 3500,1469.99 3475,1494.99
  Layer 6 - Bottom Layer w5: R133.1@3225,688.62 v1(3225,1055)
NetR134_1: R134.1 U13.K25 | length 542.2
  Layer 1 - Top Layer w5: R134.1@2795,1453.62 2795,1509.33 2857.16,1571.5 2862.35,1571.5 2945.85,1655 3035.85,1655 3095.59,1714.74 3167.74,1714.74 3176.23,1723.23 U13.K25@3192.91,1723.23
NetR135_1: R135.1 U13.J20 | length 597.5
  Layer 1 - Top Layer w4: v3(3307.1,1707.4) U13.J20@3320.8,1697.6
  Layer 4 - Signal / PWR w4: 3163,1581.51 3190,1608.51 3190,1630 3213.93,1653.93 3292.63,1653.93 3318.19,1679.49 3318.19,1696.31 v3(3307.1,1707.4)
  Layer 4 - Signal / PWR w5.25: v1(2922,1453.51) 2948.49,1480 3009.58,1480 3039.96,1510.38 3083.37,1510.38 ; 3083.38,1510.37 3091.86,1510.37 3163,1581.51
  Layer 6 - Bottom Layer w5: R135.1@2920,1408.62 2922,1410.63 v1(2922,1453.51)
NetR136_2: R136.2 U5.33 | length 104.5
  Layer 6 - Bottom Layer w5: R136.2@5072.56,2400.31 5080,2407.76 5080,2425.31 5105.47,2450.79 U5.33@5145.83,2450.79
NetR137_2: R137.2 U5.31 | length 143
  Layer 6 - Bottom Layer w5: R137.2@5072.56,2310.31 5095,2332.76 5095,2345.31 5120,2370.31 5120,2405.31 5126.1,2411.42 U5.31@5145.83,2411.42
NetR138_2: R138.2 U5.36 | length 113.7
  Layer 6 - Bottom Layer w5: R138.2@5042.56,2535 5075,2535 5100.16,2509.84 U5.36@5145.83,2509.84
NetR139_2: R139.2 U5.37 | length 104.5
  Layer 6 - Bottom Layer w5: R139.2@5072.56,2580 5080,2572.56 5080,2555 5105.47,2529.53 U5.37@5145.83,2529.53
NetR140_2: R140.2 U5.38 | length 158.1
  Layer 6 - Bottom Layer w5: R140.2@5042.56,2625 5080,2625 5105,2600 5105,2560 5115.79,2549.21 U5.38@5145.83,2549.21
NetR141_2: R141.2 U5.39 | length 143
  Layer 6 - Bottom Layer w5: R141.2@5072.56,2670 5095,2647.56 5095,2635 5120,2610 5120,2575 5126.1,2568.9 U5.39@5145.83,2568.9
NetR142_2: R142.2 U5.34 | length 113.7
  Layer 6 - Bottom Layer w5: R142.2@5042.56,2445.31 5075,2445.31 5100.16,2470.47 U5.34@5145.83,2470.47
NetR143_2: R143.2 U5.32 | length 158.1
  Layer 6 - Bottom Layer w5: R143.2@5042.56,2355.31 5080,2355.31 5105,2380.31 5105,2420.31 5115.79,2431.1 U5.32@5145.83,2431.1
NetR146_1: R146.1 U2.5 | length 63
  Layer 1 - Top Layer w10: R146.1@1245,1280 1276.61,1248.39 U2.5@1294.88,1248.39
NetR148_1: R148.1 U9.35 | length 88
  Layer 1 - Top Layer w5: R148.1@5306.5,1390 5307,1390 5339.94,1422.94 U9.35@5380.83,1422.94
NTRST: J4.9 R50.1 R56.2 | length 137.4
  Layer 1 - Top Layer w5: J4.9@3806.7,512.8 R56.2@3806.7,601.3
  Layer 1 - Top Layer w5.25: R56.2@3805,607.01 v1(3805,625)
  Layer 6 - Bottom Layer w5.25: v1(3805,625) 3805,627 3814.38,636.38 R50.1@3830,636.38
"PMIC EN": R60.1 TP19.1 U17.19 U25.6 U26.6 | length 10195.5
  Layer 1 - Top Layer w5: U26.6@2891.54,739.37 v2(2935,739.37) ; v2(3610,2575) 3700,2575 3780,2495 3780,2415 3930,2265 4090,2265 4165,2190 4469.37,2190 4489.37,2210 U25.6@4489.37,2358.46
  Layer 1 - Top Layer w10: v1(1086.5,2921.5) 1103.31,2904.69 U17.19@1138.19,2904.69 ; v1(2105,2780) 2104.72,2780.28 R60.1@2104.72,2820 TP19.1@2180,2820
  Layer 6 - Bottom Layer w5: v2(2935,739.37) 2925.63,730 2690,730 2650,770 2535,770 2505,740 2505,315 2440,250 1050,250 945,355 945,1205 850,1300 850,1620 945,1715 1465,1715 1495,1745 1495,2474.85 1760.15,2740 2065,2740 v1(2105,2780) 2745,2780 2790,2825 3360,2825 v2(3610,2575)
  Layer 6 - Bottom Layer w10: v1(1086.5,2921.5) 1198,2810 1290,2810 1345,2865 2020,2865 v1(2105,2780)
RD+: R11.1 T1.6 U5.12 U8.1 | length 755.3
  Layer 1 - Top Layer w4.4: v1(5679.96,2525) T1.6@5727.48,2525
  Layer 3 - Signal / PWR w4.5: v1(5410,2564.06) 5397.94,2564.06 5389,2573 5376,2573 5357,2592 5357,2631.8 5379.2,2654 5465.8,2654 5490,2629.8 5490,2526 5515,2501 5628.8,2501 5645.8,2484 5669.96,2484 5679.96,2494 v1(5679.96,2525)
  Layer 6 - Bottom Layer w4.5: U5.12@5374.17,2568.9 5392.1,2568.9 5396.94,2564.06 v1(5410,2564.06) 5420.94,2575 R11.1@5447.44,2575 ; U8.1@5679.69,2550 5679.69,2525.28 v1(5679.96,2525)
RD-: R12.2 T1.8 U5.11 U7.1 | length 738.6
  Layer 1 - Top Layer w4.4: v1(5679.96,2425) T1.8@5727.48,2425
  Layer 3 - Signal / PWR w4.5: v1(5410,2593.43) 5397.43,2593.43 5391,2587 5381.8,2587 5371,2597.8 5371,2626 5385,2640 5460,2640 5476,2624 5476,2520.2 5509.2,2487 5623,2487 5640,2470 5669.96,2470 5679.96,2460 v1(5679.96,2425)
  Layer 6 - Bottom Layer w4.4: v1(5410,2593.43) 5420,2603.43 5420,2618.43 5425,2623.43 R12.2@5447.44,2623.43
  Layer 6 - Bottom Layer w4.5: U5.11@5374.17,2588.58 5391.58,2588.58 5396.43,2593.43 v1(5410,2593.43) ; U7.1@5679.69,2460 5679.96,2459.72 v1(5679.96,2425)
REGEN1: R93.1 U25.26 U27.3 | length 1881
  Layer 1 - Top Layer w5: v1(4305,2420) 4315.31,2430.31 U25.26@4358.46,2430.31
  Layer 1 - Top Layer w8: U27.3@2759.84,2962.6 2759.84,2935.16 2775,2920 v1(2775,2905)
  Layer 6 - Bottom Layer w5: v1(2775,2905) 2808.62,2905 2810,2903.62 2810,2855 2825,2840 3380,2840 3665,2555 4170,2555 v1(4305,2420)
"RJ45 GND": C131.2 C132.2 C145.2 C201.2 H2.1 J2.S1 J2.S2 R95.1
  other v1: 6140,1925 6140,1955 6140,1985 6120,2020 6120,2050 6120,2080 6105,2115 6105,2145 6105,2175 6105,2205 6105,2235 6350,2950 6380,2950 6410,2950 6440,2950 6470,2950 6120,2975 6120,3005 6120,3035
RSTOUTN: R127.2 U13.E20 U16.3 | length 2973.4
  Layer 1 - Top Layer w4: v3(3294.9,1577.6) U13.E20@3320.8,1595.2
  Layer 1 - Top Layer w5: v1(4450,670) 4870,670 4887.01,687.01 R127.2@4887.01,755 4887.01,902.01 4910,925 U16.3@5082.01,925
  Layer 4 - Signal / PWR w4: v3(3294.9,1577.6) 3316,1577.6 3322.69,1570.91 3322.69,1522.69
  Layer 4 - Signal / PWR w5.25: 3322.69,1522.69 3322.69,1502.69 3170,1350 3170,1170 3237.49,1102.51 3432.49,1102.51 3480,1055 4230,1055 4440,845 4440,680 v1(4450,670)
RX+: J2.3 T1.11 | length 770.2
  Layer 1 - Top Layer w4.4: T1.11@6062.52,2525 6082,2525 6125,2482 6147.8,2482 6169,2460.8 6169,2386 6195,2360 6340,2360 6370,2390 6370,2559 6359,2570 6291,2570 6280,2559 6280,2534 6289,2525 J2.3@6321.26,2525
RX-: J2.6 T1.9 | length 851.5
  Layer 1 - Top Layer w4.4: T1.9@6062.52,2425 6082,2425 6125,2468 6142,2468 6155,2455 6155,2380.2 6189.2,2346 6345.8,2346 6384,2384.2 6384,2564.8 6364.8,2584 6290,2584 6270,2604 6270,2626.26 J2.6@6221.26,2675
RX_CLK_1: R29.1 U13.E11 | length 3564.7
  Layer 1 - Top Layer w4: v3(3538.7,1585.3) U13.E11@3551.18,1595.28
  Layer 1 - Top Layer w5: v6(5195,1675) 5270,1600 R29.1@5317.01,1600
  Layer 6 - Bottom Layer w4: v3(3538.7,1585.3) 3553.3,1585.3 3563,1575.6 3563,1515.31
  Layer 6 - Bottom Layer w5: 3563,1515.31 3563,1507 3610,1460 3610,1110 3650,1070 3805,1070 3905,970 3905,875 3970,810 4405,810 4552.68,662.32 5177.32,662.32 5260,745 5260,1385 5220,1425 5220,1650 v6(5195,1675)
RX_CTRL_1: U9.15 U13.F11 | length 4312.5
  Layer 1 - Top Layer w4: v3(3538.6,1630.7) 3551.16,1620.83 U13.F11@3551.2,1620.8
  Layer 1 - Top Layer w5: U9.15@5609.17,1501.68 5631.69,1501.68 5640,1510 5640,1625 v6(5610,1655)
  Layer 3 - Signal / PWR w4: v3(3538.6,1630.7) 3554.3,1630.7 3565,1620 3565,1600 3555,1590 3555,1480 3571,1464
  Layer 3 - Signal / PWR w5.25: v1(3570,985) 3570,1035 3590,1055 3590,1445 3571,1464
  Layer 6 - Bottom Layer w5: v1(3570,985) 3605,950 3730,950 3790,890 3790,850 3930,710 3955,710 4035,630 4035,605 4090,550 5105,550 5165,490 5266.27,490 5360,583.73 5360,1431.27 5326,1465.27 5326,1605 5361,1640 5477.5,1640 5492.5,1655 v6(5610,1655)
RX_D0_1: U9.26 U13.D13 | length 3923.6
  Layer 1 - Top Layer w4: U13.D13@3500,1569.69 v3(3513.4,1560.6)
  Layer 1 - Top Layer w5: v6(5275,1675) 5325,1625 5425,1625 5435.94,1614.06 U9.26@5435.94,1596.17
  Layer 6 - Bottom Layer w4: 3504.5,1507.93 3497.91,1514.52 3497.91,1544.71 3513.4,1560.2 v3(3513.4,1560.6)
  Layer 6 - Bottom Layer w5: 3504.5,1507.93 3515,1497.43 3515,1485.59 3531,1469.59 3531,1079 3620,990 3785,990 3828,947 3828,862 3950,740 3975,740 4065,650 4065,625 4099,591 5124,591 5184,531 5249.28,531 5320,601.72 5320,1413.28 5275,1458.28 v6(5275,1675)
RX_D1_1: R9.1 U9.25 U13.C13 | length 3953.5
  Layer 1 - Top Layer w4: U13.C13@3500,1544.09 v3(3512.9,1533.6)
  Layer 1 - Top Layer w5: v6(5315,1675) 5350,1640 5440,1640 5455.63,1624.37 U9.25@5455.63,1596.17
  Layer 6 - Bottom Layer w4: v3(3512.9,1533.6) 3513,1513 3517.02,1508.98
  Layer 6 - Bottom Layer w5: 3517.02,1508.98 3527.7,1498.3 3527.7,1490.58 3543,1475.28 3543,1092 3625,1010 3790,1010 3845,955 3845,865.36 3955.36,755 3985,755 4080.36,659.64 4080.36,630 4099.36,611 5134,611 5194,551 5241,551 5300,610 5300,1405 5250,1455 5250,1700 5262.01,1712.01 R9.1@5315,1712.01 v6(5315,1675)
RX_D2_1: R147.1 U9.24 U13.E13 | length 3969.1
  Layer 1 - Top Layer w4: U13.E13@3500,1595.28 v3(3513.6,1586.7)
  Layer 1 - Top Layer w5: v6(5355,1675) 5393.62,1675 5395,1676.38 5428.62,1676.38 5475.31,1629.68 U9.24@5475.31,1596.17
  Layer 6 - Bottom Layer w4: 3505,1477.33 3489.92,1512.88 3489.92,1563.02 v3(3513.6,1586.7)
  Layer 6 - Bottom Layer w5: 3505,1477.33 3518,1464.33 3518,1067 3615,970 3735,970 3810,895 3810,855 3940,725 3965,725 4050,640 4050,615 4094,571 5113.7,571 5173.7,511 5257.57,511 5340,593.43 5340,1421.57 5305,1456.57 5305,1625 v6(5355,1675)
RX_D3_1: U9.23 U13.B13 | length 4377.9
  Layer 1 - Top Layer w4: U13.B13@3500,1518.5 3512.7,1505.8 3512.7,1464
  Layer 1 - Top Layer w5: 3512.7,1464 3512.7,1452.7 3470,1410 3410,1410 3390,1390 3390,845 3439,796 3790.56,796 4011.56,575 v1(5205,575) ; v6(5465,1675) 5495,1645 U9.23@5495,1596.17
  Layer 6 - Bottom Layer w5: v1(5205,575) 5235,575 5280,620 5280,1395 5235,1440 5235,1760 5265,1790 5440,1790 5465,1765 v6(5465,1675)
SPIMEM_CLK: R38.2 R39.2 R40.1 | length 276.2
  Layer 1 - Top Layer w5: R40.1@4450,945.51 4455,940.51 4455,840 4470,825 R38.2@4572.44,825 R39.2@4572.44,780
SPIMEM_CSN: R124.2 U13.G4 U16.7 | length 1905.6
  Layer 1 - Top Layer w4: U13.G4@3730.31,1646.46 3723.99,1636.89 3722.2,1631.41 3722.2,1623.81 3726.07,1618.04 3738.3,1605.81 v3(3742,1605.81)
  Layer 1 - Top Layer w5: v2(4215,1365) 4950,1365 4975,1340 4975,1150 5000,1125 U16.7@5082.01,1125 5162.56,1125 R124.2@5165,1127.44
  Layer 4 - Signal / PWR w5.25: v3(3742,1605.81) 3779.19,1605.81 3790,1595 3790,1564.99 3780,1555 3780,1445.45 3825.45,1400 3875,1400 3895,1420 4135,1420 4190,1365 v2(4215,1365)
SPIMEM_D0: U13.K5 U16.15 | length 1685.7
  Layer 1 - Top Layer w4: U13.K5@3704.72,1723.23 3717.1,1707.19 3718.69,1706.99 v3(3719.37,1706.11)
  Layer 1 - Top Layer w5: v2(4245,1340) 4580,1005 4580,900 4605,875 U16.15@4707.99,875
  Layer 4 - Signal / PWR w4: v3(3719.37,1706.11) 3719.37,1707.67 3745.18,1733.48 3803.72,1733.48 3837,1700.2
  Layer 4 - Signal / PWR w5.25: 3837,1700.2 3857.2,1680 4245,1680 4265,1660 4265,1535 4210,1480 4210,1410 4245,1375 v2(4245,1340)
SPIMEM_D1: U13.G2 U16.8 | length 1601.2
  Layer 1 - Top Layer w4: U13.G2@3781.5,1646.46 3794.36,1633.6 3818.9,1633.6 3822.5,1630 3837,1630
  Layer 1 - Top Layer w5: 3837,1630 3925,1630 4155,1400 4975,1400 5000,1375 5000,1195 5020,1175 U16.8@5082.01,1175
SPIMEM_D2: R33.1 U13.K6 U16.9 | length 1600.3
  Layer 1 - Top Layer w4: U13.K6@3679.13,1723.23 3687.99,1712.28 3687.81,1710.53 v3(3688.4,1709.8)
  Layer 1 - Top Layer w5: v2(4275,1340) 4290,1325 4690,1325 4707.99,1307.01 U16.9@4707.99,1175
  Layer 4 - Signal / PWR w4: v3(3688.4,1709.8) 3720.07,1741.47 3818.53,1741.47 3837,1723
  Layer 4 - Signal / PWR w5.25: 3837,1723 3865,1695 4250,1695 4280,1665 4280,1530 4225,1475 4225,1420 4275,1370 v2(4275,1340)
SPIMEM_D3: R32.1 U13.H4 U16.1 | length 2059.6
  Layer 1 - Top Layer w4: U13.H4@3730.4,1672 v3(3740.1,1685.6)
  Layer 1 - Top Layer w5.25: U16.1@5082.01,825 5082.01,750.55 R32.1@5082.56,750 v1(5082.56,720)
  Layer 3 - Signal / PWR w4: v3(3740.1,1685.6) 3755.39,1670.31 3834.69,1670.31 3845,1660
  Layer 3 - Signal / PWR w5.25: 3845,1660 4250,1255 4421.72,1255 4615,1061.72 4615,785 4720,680 5042.56,680 v1(5082.56,720)
SPIMEM_RTCLK: R39.1 U13.H3 | length 1473.5
  Layer 1 - Top Layer w4: U13.H3@3756,1672 v3(3765.6,1685.3)
  Layer 1 - Top Layer w5: R39.1@4627.56,780 v1(4660,780)
  Layer 3 - Signal / PWR w4: v3(3765.6,1685.3) 3770.34,1680.56 3837,1680.56
  Layer 3 - Signal / PWR w5.25: 3837,1680.56 3844.44,1680.56 4250,1275 4430,1275 4635,1070 4635,805 v1(4660,780)
SW_3V3: C3.1 C4.1 C6.1 C7.1 C14.2 C16.1 C17.1 C18.1 C19.1 C22.1 C23.1 C24.1 C25.1 C120.1 C141.1 C142.1 C147.1 C149.1 C150.1 C151.1 C152.1 C153.1 C154.1 C155.1 C156.1 C157.1 C199.1 C232.1 C233.1 C234.1 C235.1 C236.1 C237.1 C238.1 C252.1 C253.1 C270.1 R2.2 R3.2 R9.2 R11.2 R12.1 R13.2 R14.1 R15.1 R16.1 R18.2 R23.1 R24.1 R31.2 R32.2 R33.2 R34.1 R35.1 R41.2 R44.2 R46.2 R48.2 R91.2 R99.1 R101.2 R102.2 R109.2 R113.2 R115.2 R116.2 R120.2 R124.1 R128.1 R131.2 R132.2 R146.2 R147.2 R148.2 T1.2 T1.7 TP64.1 U5.18 U12.6 U12.7 U13.G9 U13.G10 U13.G15 U13.G17 U13.H15 U13.H17 U13.J7 U13.J8 U13.J19 U13.K8 U13.K19 U13.M7 U13.M19 U13.N7 U13.N8 U13.N19 U13.P8 U13.U7 U13.U8 U16.2 U16.14 U27.7 U27.8 | length 5811.8
  Layer 1 - Top Layer w4: 3333.2,1756.9 3333.67,1756.43 3333.67,1740.83 ; 3413.83,1633.67 3432.63,1633.67
  Layer 1 - Top Layer w5: 3413.75,1633.75 3413.83,1633.67
  Layer 1 - Top Layer w8: 3333.2,1756.9 3333.2,1761.2 U13.M19@3346.4,1774.4 ; 3333.67,1740.83 3333.67,1736.02 U13.K19@3346.46,1723.23 3337.1,1713.87 v3(3337.1,1710.4)
  Layer 1 - Top Layer w10: v3(3337.1,1710.4) U13.J19@3346.4,1697.6 ; U13.M19@3346.43,1774.43 v3(3356.6,1787.2) U13.N19@3346.46,1800 ; U13.H17@3397.64,1672.05 v3(3407.64,1659.5) U13.G17@3397.64,1646.46 3413.75,1633.75 ; 3432.63,1633.67 3448.8,1646.4 3448.84,1646.44 3458.9,1658.8 U13.H15@3448.82,1672.05 ; U13.G10@3576.77,1646.46 3576.77,1646.23 3586.5,1636.5 v3(3589.5,1636.5) 3592.5,1636.5 U13.G9@3602.4,1646.4 ; U13.K8@3627.95,1723.23 v3(3618.2,1710.3) U13.J8@3627.95,1697.64 3638.09,1687.5 v3(3641.3,1687.5) 3643.3,1686 3653.54,1696.24 U13.J7@3653.54,1697.64 3663.89,1707.12 v3(3666,1707.4) ; U13.N8@3627.95,1800 v3(3618,1812.8) U13.P8@3627.95,1825.59 ; U13.U8@3627.95,1902.36 v3(3640.79,1893.07) U13.U7@3653.54,1902.36 U13.U7@3653.6,1902.4 ; U13.M7@3653.54,1774.41 v3(3666.4,1783.8) 3653.54,1796.66 U13.N7@3653.54,1800
  Layer 1 - Top Layer w12: v2(3910,1775) C156.1@3935.31,1775
  Layer 1 - Top Layer w15: C252.1@1126.5,890 R3.2@1222.01,890 ; C253.1@1126.5,1280 R146.2@1222.01,1280 ; R31.2@3870,2848.91 v1(3895,2848.91) ; R48.2@4005,2833.91 v1(4030,2833.91) ; v1(4080,977.01) R99.1@4080,999.02 ; v1(4210.08,668) R128.1@4210.08,690.01 ; C7.1@5160,875.31 v1(5185,875.31) ; v1(5195,1390) R148.2@5243.5,1390 ; C6.1@5644.56,2900 5644.56,2750.44 5670,2725 T1.2@5727.48,2725 ; C14.2@5689.57,2300 5689.57,2370.43 5645,2415 5645,2445 5675,2475 T1.7@5727.48,2475
  Layer 1 - Top Layer w20: v1(1126.5,855) C252.1@1126.5,890 v1(1126.5,925) ; v1(1126.5,1245) C253.1@1126.5,1280 v1(1126.5,1315) ; v1(3990,854.45) R120.2@3990,894.45 ; v1(4040,854.45) R115.2@4040,894.45 ; v1(4120,854.45) R102.2@4120,894.45 ; v1(4200,854.45) R113.2@4200,894.45 ; v1(4260,854.45) R109.2@4260,894.45 ; v1(4340,854.45) R46.2@4340,894.45 ; v1(4390,854.45) R101.2@4390,894.45 ; v1(4510,854.45) R44.2@4510,894.45 ; U16.14@4707.99,925 v1(4770.98,925) ; R33.2@4762.56,1235 v2(4825,1235) ; v1(5025,720) 5025,747.56 R32.2@5027.44,750 ; U16.2@5082.01,875 C7.1@5160,875 ; R124.1@5165,1072.44 v1(5200,1072.44) ; R147.2@5400,1723.62 v1(5400,1755) ; v1(5485,1155) R34.1@5485,1193.5 ; v1(5550,1155) R35.1@5550,1193.5
  Layer 3 - Signal / PWR w6: 3414,1935 3433,1915
  Layer 3 - Signal / PWR w8: 3598.8,1645.8 3633.4,1637.2
  Layer 3 - Signal / PWR w10: 3403,1943 3414,1935 ; 3433,1915 3618.86,1915 v3(3640.79,1893.07) ; 3444,1640 3452,1652 3468,1651 ; 3502,1652 3518,1654 3547.5,1650.3
  Layer 3 - Signal / PWR w12: v1(2610,1505) 2750.01,1505 v1(2980.01,1735) 3312.5,1735 v3(3337.1,1710.4) ; 3420,1638 3444,1640
  Layer 3 - Signal / PWR w15: v3(3407.64,1659.5) 3420,1638 ; 3468,1651 3502,1652 ; 3547.5,1650.3 v3(3589.5,1636.5) 3598.8,1645.8 ; 3633.4,1637.2 3643.5,1659.5 v3(3641.3,1687.5)
  Layer 4 - Signal / PWR w15: v3(3337.1,1710.4) 3354.3,1736.8 3383.6,1736.9 3383.6,1776.6 3373,1787.2 v3(3356.6,1787.2)
  Layer 6 - Bottom Layer w5: v3@3617.92,1810.87 v3(3618,1812.8)
  Layer 6 - Bottom Layer w6: v3(3618,1812.8) 3638,1788 3648,1784 v3(3666.4,1783.8) ; 3677.93,1802.1 3697.3,1804.2
  Layer 6 - Bottom Layer w8: U5.18@5374.17,2450.79 5413.21,2450.79 C235.1@5445,2419
  Layer 6 - Bottom Layer w10: v3(3337.1,1710.4) 3337.1,1675 3347.72,1664.38 3380.66,1664.38 3385.83,1659.5 v3(3407.64,1659.5) ; v3(3640.79,1893.07) 3647.72,1900 3705,1900 3725,1920 3745,1920 ; v3(3666.4,1783.8) 3666.4,1795.4 3673.1,1802.1 3677.93,1802.1 ; 3697.3,1804.2 3715.7,1806.2
  Layer 6 - Bottom Layer w12: v1(2610,1505) R116.2@2687.01,1505 ; v1(2980.01,1735) C149.1@2980.01,1764.99 ; v1(3447.3,2159.65) 3452.65,2165 C153.1@3480,2165 ; C153.1@3479,2164.68 C155.1@3515,2164.68 ; v1(3516,2187) C155.1@3515,2164.68 ; v1(3534.69,2164.68) C155.1@3515,2164.68 ; 3715.7,1806.2 3726,1804.1 3782.4,1802.1 ; v2(3910,1775) C157.1@3935.31,1775
  Layer 6 - Bottom Layer w15: C152.1@3310,1740 3310.14,1739.84 v3(3337.1,1710.4) ; 3745,1920 C154.1@3860,1920 ; 3782.4,1802.1 3809.5,1775 v2(3910,1775) ; R91.2@3915,2499.69 v2(3915,2525) ; v2(4615,2810) R41.2@4645.31,2810 ; v1(5240,2258) R16.1@5240,2285.01 ; v2(5275,1755) 5292.01,1737.99 R9.2@5315,1737.99 ; v1(5310,2258) R18.2@5310,2285.01 ; v2(5390,1295) R2.2@5390,1327.01
  Layer 6 - Bottom Layer w50: 4110,1510 4570,1510 4765,1315 4885,1315
  other v1: 5660,1093 5660,1123 5660,1153 5660,1183 5660,1228 5660,1273 5570,1702 5570,1747 5570,1792 5550,1852 5550,1882 5550,1912 3545,2187 5675,2260 5705,2260 5575,2380 5605,2380 5635,2380 5540,2463 5565,2463 5540,2633 5565,2633 5125,2788 5125,2818 4435,2830 4465,2830 5125,2848 5125,2878 5629.13,2940 5659.13,2940 3405,3065 3435,3065 3405,3095 3435,3095 2660,3140 2690,3140 2660,3170 2690,3170 2660,3200 2690,3200
  other v2: 4825,1300 4855,1300 4885,1300 4825,1330 4855,1330 4885,1330 4110,1495 4140,1495 4170,1495 4110,1525 4140,1525 4170,1525 3636,2154.27 3636,2194.27 3636,2234.27 3636,2274.27 3935,3135 3965,3135 3995,3135 4025,3135 3935,3165 3965,3165 3995,3165 4025,3165
SYS_3V3: 3.3V.1 C173.1 C174.1 C177.1 C179.1 C184.1 C228.1 C229.1 C230.1 C241.1 C242.1 C243.1 C247.1 C251.1 C255.1 C256.1 C257.1 C258.1 C260.1 C261.1 C262.1 C264.1 C265.1 C266.1 C269.1 L5.2 L6.1 R49.2 R50.2 R51.2 R52.2 R53.2 R54.2 R55.2 R60.2 R61.2 R70.2 R96.1 TP50.1 TP52.1 U17.22 U18.4 U18.6 U19.10 U25.5 U25.11 U25.12 U25.24 U25.25 U26.5 U26.8 U26.11 U26.12 U26.24 U26.25 U26.28 U27.1 U27.2 | length 3118.7
  Layer 1 - Top Layer w8: U26.28@2859.06,608.46 2859.06,585.94 2875,570 C264.1@2902.44,570 ; U26.8@2859.06,791.54 2859.06,814.06 2875,830 C265.1@2902.44,830 ; U26.5@2891.54,719.68 2925.32,719.68 2930,715 2964.68,715 C266.1@2965,714.68 ; C247.1@4464.69,2285 4465,2285.32 4465,2320 4469.69,2324.68 U25.5@4469.69,2358.46
  Layer 1 - Top Layer w10: v1(1095,2845.63) U17.22@1138.19,2845.63 ; U18.4@1360.59,2043.39 1360.59,2055.59 v1(1385,2080)
  Layer 1 - Top Layer w20: v1(2021.38,216.38) R96.1@2065,216.38 ; C264.1@2900,572.44 v2(2900,600) ; v2(2900,800) 2900,827.56 C265.1@2902.44,830 ; C266.1@2965,714.68 2989.68,714.68 v2(2990,715) ; R52.2@3988.62,175 v2(4045,175) ; R51.2@3988.62,220 v2(4045,220) ; C247.1@4464.69,2285 4464.69,2260.32 v2(4465,2260)
  Layer 3 - Signal / PWR w20: v2(4465,2260) 4509.54,2304.54 4577.54,2304.54 4715,2442 v2(4715,2485)
  Layer 6 - Bottom Layer w10: v1(1095,2845.63) 1055.67,2845.63 1025,2876.3 1025,3205 1070,3250 1790,3250 v1(1840,3200)
  Layer 6 - Bottom Layer w20: R53.2@3675.38,684 R54.2@3719.62,684 ; R54.2@3720,683.62 3741.38,705 3808.62,705 R50.2@3830,683.62 ; R50.2@3830.38,684 R55.2@3874.62,684 ; R55.2@3875.38,684 R49.2@3919.62,684 ; R49.2@3920,683.62 3941.38,683.62 3970,655 3970,460 v2(3980,450) v2(4005,425) v2(4030,400) 4045,385 v2(4045,220) v2(4045,175)
  other v1: 2225,355 2260,355 2295,355 1165,2190 1195,2190 1225,2190 1165,2220 1195,2220 1225,2220 1165,2250 1195,2250 1225,2250 4300,2740 4330,2740 4360,2740 4550,2740 4580,2740 4610,2740 4300,2770 4330,2770 4360,2770 4550,2770 4580,2770 4610,2770 2705,2825 2735,2825 2705,2855 2735,2855 2070,2945 2100,2945 2130,2945 2070,2975 2100,2975 2130,2975 2070,3005 2100,3005 2130,3005
  other v2: 2765,265 2830,265 2765,295 2830,295 2765,375 2833.7,375 2765,405 2833.7,405 2765,995 2833.7,995 2765,1025 2833.7,1025 2765,1105 2830,1105 2765,1135 2830,1135 4035,2485 4065,2485 4095,2485 4125,2485 4155,2485 4185,2485 4745,2485 4775,2485 4805,2485 4835,2485 4865,2485 4065,2515 4155,2515 4745,2515 4835,2515
SYS_5V0: 5V.1 C5.1 C29.1 C30.1 C180.1 C189.1 C195.1 C245.1 C246.1 U1.3 U2.3 U3.3 U18.2 U18.3 U25.8 U25.28 U27.4 | length 1502.9
  Layer 1 - Top Layer w8: U27.4@2779.53,2962.6 2779.53,2945.47 2880,2845 v1(2880,2710) ; C245.1@4320,2347.56 4320,2375 4335.94,2390.94 U25.28@4358.46,2390.94 ; U25.8@4541.54,2390.94 4564.06,2390.94 4580,2375 C246.1@4580,2347.56
  Layer 1 - Top Layer w20: C245.1@4320,2347.56 4322.44,2350 v2(4350,2350) ; v2(4550,2350) 4577.56,2350 C246.1@4580,2347.56
  Layer 3 - Signal / PWR w20: v2(3625,2515) v2(3655,2515) 3807.76,2515 3972.76,2350 v2(4350,2350) 4360,2360 4540,2360 v2(4550,2350)
  other v1: 1590,870 1590,900 1580,1227.4 1580,1257.4 1435,1825 1465,1825 1435,1855 1465,1855 1435,1885 1465,1885
SYS_CLK1: R30.2 R98.2 U13.Y12 | length 1039.3
  Layer 1 - Top Layer w4: 3490,2100 3480,2090 3480,2035 3468.73,2023.73 3468.73,2009.71 3486.49,1991.95 3491.98,1991.95 3512.79,1991.93 U13.Y12@3525.59,1979.13
  Layer 1 - Top Layer w5: 3490,2100 3490,2588 3544.23,2636.5 R98.2@3790,2636.5 3852.01,2636.5 R30.2@3853.5,2635
SYSBOOT0: R100.2 U13.F1 | length 949.7
  Layer 1 - Top Layer w4: U13.F1@3807.09,1620.87 3834.23,1620.87 3837,1618.1
  Layer 1 - Top Layer w5: 3837,1618.1 3916.9,1618.1 R100.2@4510,1025
SYSBOOT1: R104.2 U13.E2 | length 859.1
  Layer 1 - Top Layer w4: U13.E2@3781.5,1595.28 3794.28,1582.5 3837,1582.5
  Layer 1 - Top Layer w5: 3837,1582.5 3892.5,1582.5 4340,1135 R104.2@4340,1025
SYSBOOT2: R108.2 U13.E1 | length 866
  Layer 1 - Top Layer w4: U13.E1@3807.09,1595.28 3837,1595.28
  Layer 1 - Top Layer w5: 3837,1595.28 3899.72,1595.28 4390,1105 R108.2@4390,1025
SYSBOOT3: R112.2 U13.C1 | length 686.1
  Layer 1 - Top Layer w4: U13.C1@3807.09,1544.09 3837,1544.09
  Layer 1 - Top Layer w5: 3837,1544.09 3870.91,1544.09 4120,1295 R112.2@4120,1025
SYSBOOT4: R118.2 U13.D1 | length 778.1
  Layer 1 - Top Layer w4: U13.D1@3807.09,1569.69 3837,1569.69
  Layer 1 - Top Layer w5: 3837,1569.69 3885.31,1569.69 4260,1195 R118.2@4260,1025
SYSBOOT5: R122.2 U13.D2 | length 767.1
  Layer 1 - Top Layer w4: U13.D2@3781.5,1569.69 3794.39,1556.8 3837,1556.8
  Layer 1 - Top Layer w5: 3837,1556.8 3878.2,1556.8 4200,1235 R122.2@4200,1025
SYSBOOT6: R126.2 U13.B1 | length 618.9
  Layer 1 - Top Layer w4: U13.B1@3807.09,1518.5 3837,1518.5
  Layer 1 - Top Layer w5: 3837,1518.5 3856.5,1518.5 4040,1335 R126.2@4040,1025
SYSBOOT7: R129.2 U13.B2 | length 613.6
  Layer 1 - Top Layer w4: U13.B2@3781.5,1518.5 3790.1,1518.5 3798.69,1505.8 3849.2,1505.8
  Layer 1 - Top Layer w5: 3849.2,1505.8 3990,1365 R129.2@3990,1025
SYSBOOT8: R99.2 U13.C2 | length 683.4
  Layer 1 - Top Layer w4: U13.C2@3781.5,1544.09 3794.39,1531.2 3837,1531.2
  Layer 1 - Top Layer w5: 3837,1531.2 3863.8,1531.2 4080,1315 R99.2@4080,1025
SYSBOOT9: R103.2 U13.D3 | length 1141.7
  Layer 1 - Top Layer w4: U13.D3@3756.01,1569.6 v3(3765.9,1582.3)
  Layer 1 - Top Layer w5: R103.2@4165.08,715.99 v1@4165.08,739.92
  Layer 3 - Signal / PWR w4: v3(3765.9,1582.3) 3799.5,1582.3 3817.67,1564.13 3837,1564.13
  Layer 3 - Signal / PWR w5.25: 3837,1564.13 3859.87,1564.13 4190,1234 4190,1025 4225,990 4225,830 4165,770 v1(4165,740)
SYSBOOT10: R107.2 U13.A2 | length 1253.7
  Layer 1 - Top Layer w4: 3781.5,1464 U13.A2@3781.5,1492.91
  Layer 1 - Top Layer w5: 3781.5,1464 3781.5,1443.95 3935,1290.45 3935,935 3910,910 3910,850 3945,815 4325,815 4345.08,794.92 R107.2@4345.08,715.99
SYSBOOT11: R111.2 U13.B3 | length 1253.6
  Layer 1 - Top Layer w4: U13.B3@3755.91,1518.5 3755.91,1510.98 3768.7,1498.19 3768.7,1464
  Layer 1 - Top Layer w5: 3768.7,1464 3768.7,1442.6 3920,1291.3 3920,940 3895,915 3895,840 3935,800 4285,800 4300.08,784.92 R111.2@4300.08,715.99
SYSBOOT12: R117.2 U13.C3 | length 1361.2
  Layer 1 - Top Layer w4: U13.C3@3755.91,1544.09 3768.8,1531.2 3768.8,1512.4 3775.5,1505.7 3786.8,1505.7 3794.3,1498.2 3794.3,1465
  Layer 1 - Top Layer w5: 3794.3,1465 3794.3,1445.7 3950,1290 3950,930 3925,905 3925,860 3955,830 4370,830 4390.08,809.92 R117.2@4390.08,715.99
SYSBOOT13: R121.2 U13.C4 | length 1097.6
  Layer 1 - Top Layer w4: U13.C4@3730.42,1544.01 v3(3740.2,1556.6)
  Layer 1 - Top Layer w5: v1(4120,740) 4120.08,739.92 R121.2@4120.08,715.99
  Layer 3 - Signal / PWR w4: v3(3740.2,1556.6) 3792.99,1556.6 3805.96,1543.63 3825.37,1543.63 3837,1532
  Layer 3 - Signal / PWR w5.25: 3837,1532 4150,1219 4150,935 4130,915 4130,880 4150,860 4150,805 4120,775 v1(4120,740)
SYSBOOT14: R125.2 U13.A3 | length 1165.3
  Layer 1 - Top Layer w4: 3755.91,1464 U13.A3@3755.91,1492.91
  Layer 1 - Top Layer w5: 3755.91,1464 3755.91,1441.24 3880,1317.15 3880,835 3930,785 4240,785 4255.08,769.92 R125.2@4255.08,715.99
SYSBOOT15: R128.2 U13.B4 | length 1159.4
  Layer 1 - Top Layer w4: U13.B4@3730.31,1518.5 3743.22,1505.59 3743.22,1464
  Layer 1 - Top Layer w5: 3743.22,1464 3743.22,1439.78 3865,1318 3865,830 3925,770 4195,770 4210.08,754.92 R128.2@4210.08,715.99
TD+: R13.1 T1.1 U4.1 U5.15 | length 805.7
  Layer 1 - Top Layer w4.4: v1(5679.96,2775) T1.1@5727.48,2775
  Layer 3 - Signal / PWR w4.5: v1(5410,2505) 5403,2512 5388.2,2512 5320,2580.2 5320,2674.8 5379.2,2734 5669.96,2734 5679.96,2744 v1(5679.96,2775)
  Layer 6 - Bottom Layer w4.4: v1(5410,2505) 5420.56,2494.44 5438,2494.44 R13.1@5457.44,2475
  Layer 6 - Bottom Layer w4.5: U5.15@5374.17,2509.84 5392.16,2509.84 5397,2505 v1(5410,2505) ; U4.1@5679.69,2800 5679.96,2799.73 v1(5679.96,2775)
TD-: R14.2 T1.3 U5.14 U6.1 | length 750.3
  Layer 1 - Top Layer w4.4: v1(5679.96,2675) T1.3@5727.48,2675
  Layer 3 - Signal / PWR w4.5: v1(5410,2534.37) 5401.63,2526 5394,2526 5334,2586 5334,2669 5385,2720 5669.96,2720 5679.96,2710 v1(5679.96,2675)
  Layer 6 - Bottom Layer w4.4: v1(5410,2534.37) 5419.37,2525 R14.2@5447.44,2525
  Layer 6 - Bottom Layer w4.5: U5.14@5374.17,2529.53 5391.53,2529.53 5396.37,2534.37 v1(5410,2534.37) ; U6.1@5679.69,2650 U6.1@5679.96,2650.28 ; U6.1@5679.96,2645.28 U6.1@5679.96,2650.28 ; v1(5679.96,2675) U6.1@5679.96,2650.28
